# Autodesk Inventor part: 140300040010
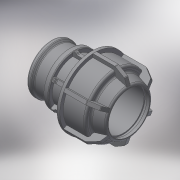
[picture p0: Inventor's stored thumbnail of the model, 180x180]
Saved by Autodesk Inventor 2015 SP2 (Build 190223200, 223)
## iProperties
Created: 2017-08
Part Number: 140300040010
Material: Generic
Description: PLASSON L.14 FEMALE ADAPTOR (SILVER) 40-1"
Document SubType Name: Modeling
Designer: KIM
Density: 1 g/cm^3
Appearance: Default
Author: KIM
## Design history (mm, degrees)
derived "140300.ipt"
feature "Solid1::140300.ipt"
tag "TaggingFeature1"
body "Solid1"
other parameters: "d2" = 73, "d4" = 15 deg, "d5" = 48.18, "d6" = 15.8994, "d9" = 30.291, "d10" = 73, "d11" = 39.3783, "d12" = 36.3492, "d13" = 48.4656, "d14" = 21, "d16" = 40.8, "d17" = 3.65, "d18" = 97, "d19" = 6.3, "d20" = 135 deg, "d21" = 6.3, "d22" = 43.92195, "d23" = 28, "d24" = 3.65, "d25" = 65.7, "d26" = 54.75, "d27" = 3.65, "d28" = 135 deg, "d29" = 2.19, "d31" = 2, "d44" = 0.8, "d45" = 1.2, "d46" = 150 deg, "d49" = 3.65, "d50" = 0, "d51" = 0.73, "d52" = 1.46, "d53" = 45 deg, "d55" = 9.588, "d56" = 3.65, "d57" = 0, "d58" = 1.2, "d61" = 360 deg, "G_" = 30.291, "E_" = 73, "H_" = 97, "l_" = 73, "l_2" = 21, "d54" = 23.97
